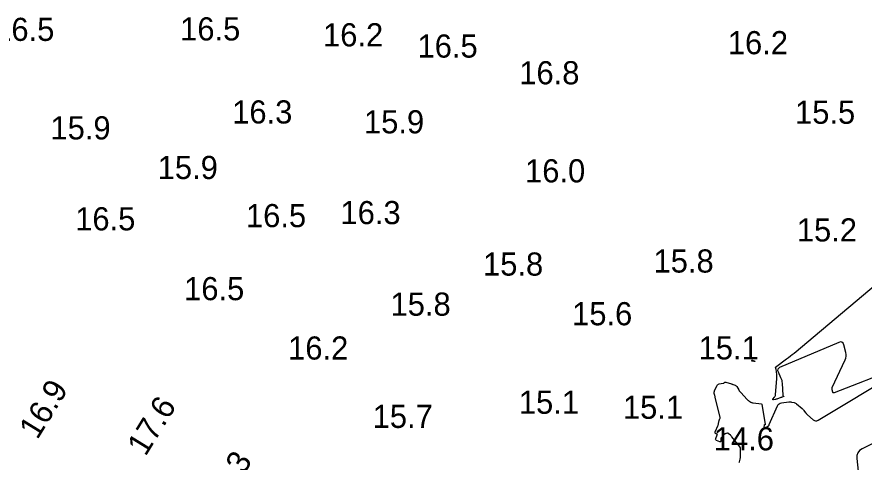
# Model space of a CAD drawing. Extents: x 1023796 to 1112670, y 656573 to 837340.
# Drawn here: x 1101696.7 to 1101879.9, y 687262.5 to 687358.7 of the extents above; entities that cross this region are included whole.
import ezdxf

# ---------------------------------------------------------------- set-up
doc = ezdxf.new("R2010")
doc.units = 0
doc.layers.add('V-CHAN-CONT-15FT', color=7, linetype='Continuous')
doc.layers.add('V-TOPO-SOUN', color=7, linetype='Continuous')

msp = doc.modelspace()

# ---------------------------------------------------------------- linework, layer by layer
at = {"layer": 'V-CHAN-CONT-15FT'}
for points in [[(1101886.75, 687282.62), (1101873.45, 687277.45), (1101873.34, 687277.43), (1101873.25, 687277.45), (1101873.19, 687277.51), (1101873.14, 687277.61), (1101873, 687278.1), (1101872.98, 687278.22), (1101872.98, 687278.35), (1101873, 687278.46), (1101873.04, 687278.58), (1101875.84, 687284.55), (1101875.99, 687284.94), (1101876.06, 687285.35), (1101876.06, 687285.76), (1101875.98, 687286.17), (1101875.51, 687287.85), (1101875.36, 687288.19), (1101875.13, 687288.39), (1101874.84, 687288.44), (1101874.48, 687288.34), (1101861.63, 687282.9), (1101861.38, 687282.74), (1101861.24, 687282.55), (1101861.21, 687282.3), (1101861.3, 687282.02), (1101861.87, 687280.8), (1101862, 687280.48), (1101862.09, 687280.17), (1101862.16, 687279.84), (1101862.2, 687279.51), (1101862.36, 687276.85), (1101862.36, 687276.82), (1101862.37, 687276.8), (1101862.39, 687276.78), (1101862.41, 687276.77), (1101862.51, 687276.72), (1101862.53, 687276.71), (1101862.53, 687276.7), (1101862.53, 687276.69), (1101862.51, 687276.67), (1101862.17, 687276.52), (1101862.1, 687276.5), (1101862.03, 687276.47), (1101861.97, 687276.44), (1101861.9, 687276.42), (1101861.07, 687276.12), (1101860.97, 687276.08), (1101860.88, 687276.06), (1101860.78, 687276.04), (1101860.68, 687276.02), (1101860.29, 687275.97), (1101860.21, 687275.96), (1101860.17, 687275.99), (1101860.17, 687276.03), (1101860.21, 687276.1), (1101860.56, 687276.54), (1101860.63, 687276.65), (1101860.68, 687276.76), (1101860.72, 687276.87), (1101860.74, 687277), (1101861.07, 687280.58), (1101861.08, 687280.78), (1101861.08, 687280.99), (1101861.07, 687281.19), (1101861.04, 687281.4), (1101860.87, 687282.6), (1101860.86, 687282.61), (1101860.86, 687282.62), (1101860.86, 687282.63), (1101860.85, 687282.65), (1101860.83, 687282.69), (1101860.83, 687282.71), (1101860.83, 687282.72), (1101860.82, 687282.73), (1101860.82, 687282.74), (1101860.81, 687282.81), (1101860.81, 687282.83), (1101860.81, 687282.85), (1101860.8, 687282.86), (1101860.8, 687282.87), (1101860.75, 687282.95), (1101860.75, 687282.97), (1101860.74, 687282.98), (1101860.75, 687283), (1101860.76, 687283.01), (1101863.17, 687284.8), (1101863.58, 687285.1), (1101863.98, 687285.42), (1101864.37, 687285.73), (1101864.77, 687286.05), (1101882.56, 687300.92)], [(1101852.93, 687262.4), (1101852.95, 687262.53), (1101853.1, 687263.11), (1101853.14, 687263.26), (1101853.16, 687263.41), (1101853.18, 687263.55), (1101853.19, 687263.7), (1101853.22, 687265.04), (1101853.21, 687265.3), (1101853.15, 687265.55), (1101853.05, 687265.79), (1101852.9, 687266.01), (1101851.34, 687267.96), (1101851.27, 687268.05), (1101851.19, 687268.14), (1101851.1, 687268.23), (1101851.01, 687268.31), (1101850.55, 687268.7), (1101850.5, 687268.73), (1101850.45, 687268.75), (1101850.4, 687268.75), (1101850.34, 687268.74), (1101850.09, 687268.64), (1101850.04, 687268.63), (1101849.98, 687268.61), (1101849.93, 687268.59), (1101849.88, 687268.57), (1101849.68, 687268.48), (1101849.63, 687268.46), (1101849.58, 687268.43), (1101849.54, 687268.4), (1101849.5, 687268.36), (1101849.05, 687267.82), (1101848.99, 687267.74), (1101848.94, 687267.65), (1101848.92, 687267.55), (1101848.91, 687267.45), (1101848.91, 687267.03), (1101848.9, 687266.94), (1101848.86, 687266.89), (1101848.8, 687266.87), (1101848.72, 687266.89), (1101848.02, 687267.17), (1101847.9, 687267.24), (1101847.83, 687267.33), (1101847.81, 687267.44), (1101847.85, 687267.58), (1101848.16, 687268.36), (1101848.18, 687268.41), (1101848.17, 687268.46), (1101848.14, 687268.51), (1101848.09, 687268.54), (1101847.81, 687268.68), (1101847.77, 687268.7), (1101847.75, 687268.73), (1101847.73, 687268.77), (1101847.73, 687268.81), (1101847.72, 687268.98), (1101847.72, 687269.02), (1101847.73, 687269.07), (1101847.74, 687269.11), (1101847.75, 687269.15), (1101848.28, 687270.33), (1101848.33, 687270.45), (1101848.37, 687270.57), (1101848.41, 687270.7), (1101848.44, 687270.83), (1101848.59, 687271.49), (1101848.6, 687271.54), (1101848.62, 687271.6), (1101848.64, 687271.65), (1101848.66, 687271.7), (1101848.75, 687271.91), (1101848.77, 687271.97), (1101848.78, 687272.02), (1101848.78, 687272.08), (1101848.77, 687272.13), (1101847.74, 687276.49), (1101847.71, 687276.59), (1101847.69, 687276.68), (1101847.66, 687276.78), (1101847.64, 687276.87), (1101847.51, 687277.33), (1101847.5, 687277.39), (1101847.49, 687277.45), (1101847.49, 687277.51), (1101847.5, 687277.58), (1101847.54, 687277.83), (1101847.56, 687277.89), (1101847.58, 687277.95), (1101847.6, 687278.01), (1101847.63, 687278.07), (1101848.12, 687279.03), (1101848.2, 687279.16), (1101848.31, 687279.26), (1101848.43, 687279.33), (1101848.58, 687279.37), (1101849.4, 687279.51), (1101849.46, 687279.52), (1101849.52, 687279.54), (1101849.57, 687279.57), (1101849.62, 687279.6), (1101849.81, 687279.74), (1101849.86, 687279.77), (1101849.92, 687279.79), (1101849.97, 687279.79), (1101850.03, 687279.78), (1101851.21, 687279.37), (1101851.32, 687279.34), (1101851.42, 687279.3), (1101851.52, 687279.26), (1101851.63, 687279.23), (1101852.04, 687279.09), (1101852.13, 687279.04), (1101852.22, 687278.99), (1101852.29, 687278.92), (1101852.36, 687278.83), (1101852.83, 687278.07), (1101852.93, 687277.92), (1101853.03, 687277.77), (1101853.15, 687277.63), (1101853.27, 687277.49), (1101854.61, 687276.01), (1101854.7, 687275.92), (1101854.8, 687275.84), (1101854.9, 687275.77), (1101855, 687275.7), (1101855.44, 687275.45), (1101855.55, 687275.39), (1101855.67, 687275.34), (1101855.78, 687275.31), (1101855.91, 687275.29), (1101857.7, 687275.07), (1101857.71, 687275.07), (1101857.71, 687275.07), (1101857.72, 687275.06), (1101857.72, 687275.06), (1101857.74, 687275.03), (1101857.75, 687275.02), (1101857.77, 687274.99), (1101857.77, 687274.98), (1101857.78, 687274.98), (1101857.78, 687274.97), (1101857.78, 687274.97), (1101858.51, 687270.62), (1101858.51, 687270.6), (1101858.51, 687270.58), (1101858.49, 687270.57), (1101858.47, 687270.57), (1101858.37, 687270.58), (1101858.35, 687270.58), (1101858.33, 687270.57), (1101858.32, 687270.55), (1101858.31, 687270.53), (1101858.23, 687269.91), (1101858.23, 687269.86), (1101858.25, 687269.84), (1101858.28, 687269.83), (1101858.32, 687269.85), (1101858.57, 687269.97), (1101858.59, 687269.98), (1101858.62, 687269.99), (1101858.65, 687270), (1101858.68, 687270.01), (1101858.79, 687270.04), (1101858.82, 687270.05), (1101858.85, 687270.06), (1101858.87, 687270.08), (1101858.9, 687270.09), (1101859.24, 687270.3), (1101859.26, 687270.31), (1101859.28, 687270.33), (1101859.3, 687270.35), (1101859.31, 687270.38), (1101859.36, 687270.48), (1101859.37, 687270.51), (1101859.38, 687270.53), (1101859.39, 687270.56), (1101859.4, 687270.58), (1101861.2, 687274.65), (1101861.35, 687274.91), (1101861.54, 687275.1), (1101861.78, 687275.23), (1101862.07, 687275.3), (1101863.63, 687275.48), (1101863.78, 687275.49), (1101863.92, 687275.49), (1101864.07, 687275.48), (1101864.22, 687275.46), (1101864.8, 687275.33), (1101864.94, 687275.29), (1101865.07, 687275.24), (1101865.2, 687275.17), (1101865.31, 687275.08), (1101866.49, 687274.07), (1101866.6, 687273.97), (1101866.71, 687273.86), (1101866.81, 687273.75), (1101866.9, 687273.63), (1101867.27, 687273.16), (1101867.36, 687273.04), (1101867.46, 687272.93), (1101867.56, 687272.82), (1101867.67, 687272.72), (1101868.92, 687271.61), (1101869.17, 687271.44), (1101869.43, 687271.37), (1101869.7, 687271.4), (1101869.97, 687271.52), (1101887.11, 687281.87)], [(1101897.82, 687274.52), (1101879.52, 687265.34), (1101878.96, 687264.96), (1101878.58, 687264.48), (1101878.38, 687263.91), (1101878.36, 687263.23), (1101878.75, 687259.15)]]:
    msp.add_lwpolyline(points, dxfattribs=at)
msp.add_lwpolyline([(1101855.73, 687284.54), (1101855.74, 687284.54), (1101855.76, 687284.53), (1101856.26, 687284.26), (1101856.27, 687284.25), (1101856.28, 687284.24), (1101856.27, 687284.23), (1101856.25, 687284.23), (1101856.16, 687284.22), (1101856.13, 687284.22), (1101856.11, 687284.22), (1101856.09, 687284.22), (1101856.06, 687284.22), (1101855.66, 687284.29), (1101855.64, 687284.3), (1101855.63, 687284.31), (1101855.62, 687284.33), (1101855.61, 687284.35), (1101855.6, 687284.45), (1101855.6, 687284.47), (1101855.61, 687284.48), (1101855.62, 687284.5), (1101855.63, 687284.51), (1101855.69, 687284.54), (1101855.71, 687284.54)], close=True, dxfattribs=at)

# ---------------------------------------------------------------- texts
at = {"layer": 'V-TOPO-SOUN'}
for s, p in [('16.5 ', (1101691.75, 687353.5)), ('16.5 ', (1101731.97, 687353.6)), ('16.2 ', (1101762.88, 687352.32)), ('16.5 ', (1101783.32, 687349.89)), ('16.2 ', (1101850.45, 687350.62)), ('16.8 ', (1101805.33, 687344.12)), ('16.3 ', (1101743.23, 687335.65)), ('15.5 ', (1101864.98, 687335.59)), ('15.9 ', (1101771.74, 687333.52)), ('15.9 ', (1101703.92, 687332.21)), ('15.9 ', (1101727.12, 687323.65)), ('16.0 ', (1101806.58, 687322.93)), ('16.5 ', (1101709.27, 687312.56)), ('16.5 ', (1101746.21, 687313.25)), ('16.3 ', (1101766.65, 687313.9)), ('15.2 ', (1101865.37, 687310.16)), ('15.8 ', (1101834.37, 687303.44)), ('15.8 ', (1101797.49, 687302.78)), ('16.5 ', (1101732.83, 687297.47)), ('15.8 ', (1101777.48, 687294.12)), ('15.6 ', (1101816.76, 687292.05)), ('16.2 ', (1101755.33, 687284.64)), ('15.1 ', (1101844.12, 687284.67)), ('15.1 ', (1101805.24, 687272.93)), ('15.1 ', (1101827.75, 687271.84)), ('15.7 ', (1101773.61, 687269.87)), ('14.6 ', (1101847.41, 687265.02))]:
    msp.add_text(s, height=5, dxfattribs=at).set_placement(p)
for s, p in [('16.9 ', (1101701.08, 687267.17)), ('17.6 ', (1101724.48, 687263.56)), ('17.3 ', (1101740.88, 687251.72))]:
    msp.add_text(s, height=5, rotation=58.4285, dxfattribs=at).set_placement(p)

doc.saveas('drawing.dxf')
